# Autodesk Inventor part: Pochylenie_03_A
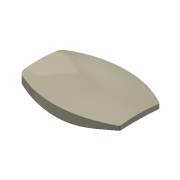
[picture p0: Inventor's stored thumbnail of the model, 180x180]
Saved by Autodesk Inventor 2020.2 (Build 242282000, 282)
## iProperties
Created: 2005-05
Part Number: Pochylenie_03_A
Document SubType Name: Modeling
Designer: F.Stasiak
Manufacturer: Standard
Standards Organization: Custom
Stock Number: Ćwiczenie_5_54a
Density: 1 g/cm^3
Material: Ogólny
Appearance: Jasnobeżowa
Manager: www.cadconsulting.pl
Company: Fabian Stasiak CAD Consulting
Author: F.Stasiak
Subject: Zbiór ćwiczeń. Autodesk Inventor 2020. Kurs podstawowy
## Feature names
1. Wyciągnięcie proste1 [Extrusion]
2. Zaokrąglenie1 [Fillet]
3. Podział4
## Parameters: d4 = 0, d5 = 0, d10 = 15 mm, d11 = 5 mm, d12 = 0, d16 = 0, d17 = 0
